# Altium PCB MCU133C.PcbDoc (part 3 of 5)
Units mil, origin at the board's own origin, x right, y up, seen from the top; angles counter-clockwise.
Board outline 2300 x 5500 mil, 4 copper layers (Top Signal, GND, PWR, Bottom Signal), stack 61.6 mil thick; 278 components, 226 nets, 1057 pads, 868 vias.
Unrouted connection lines stored in the file: 237.
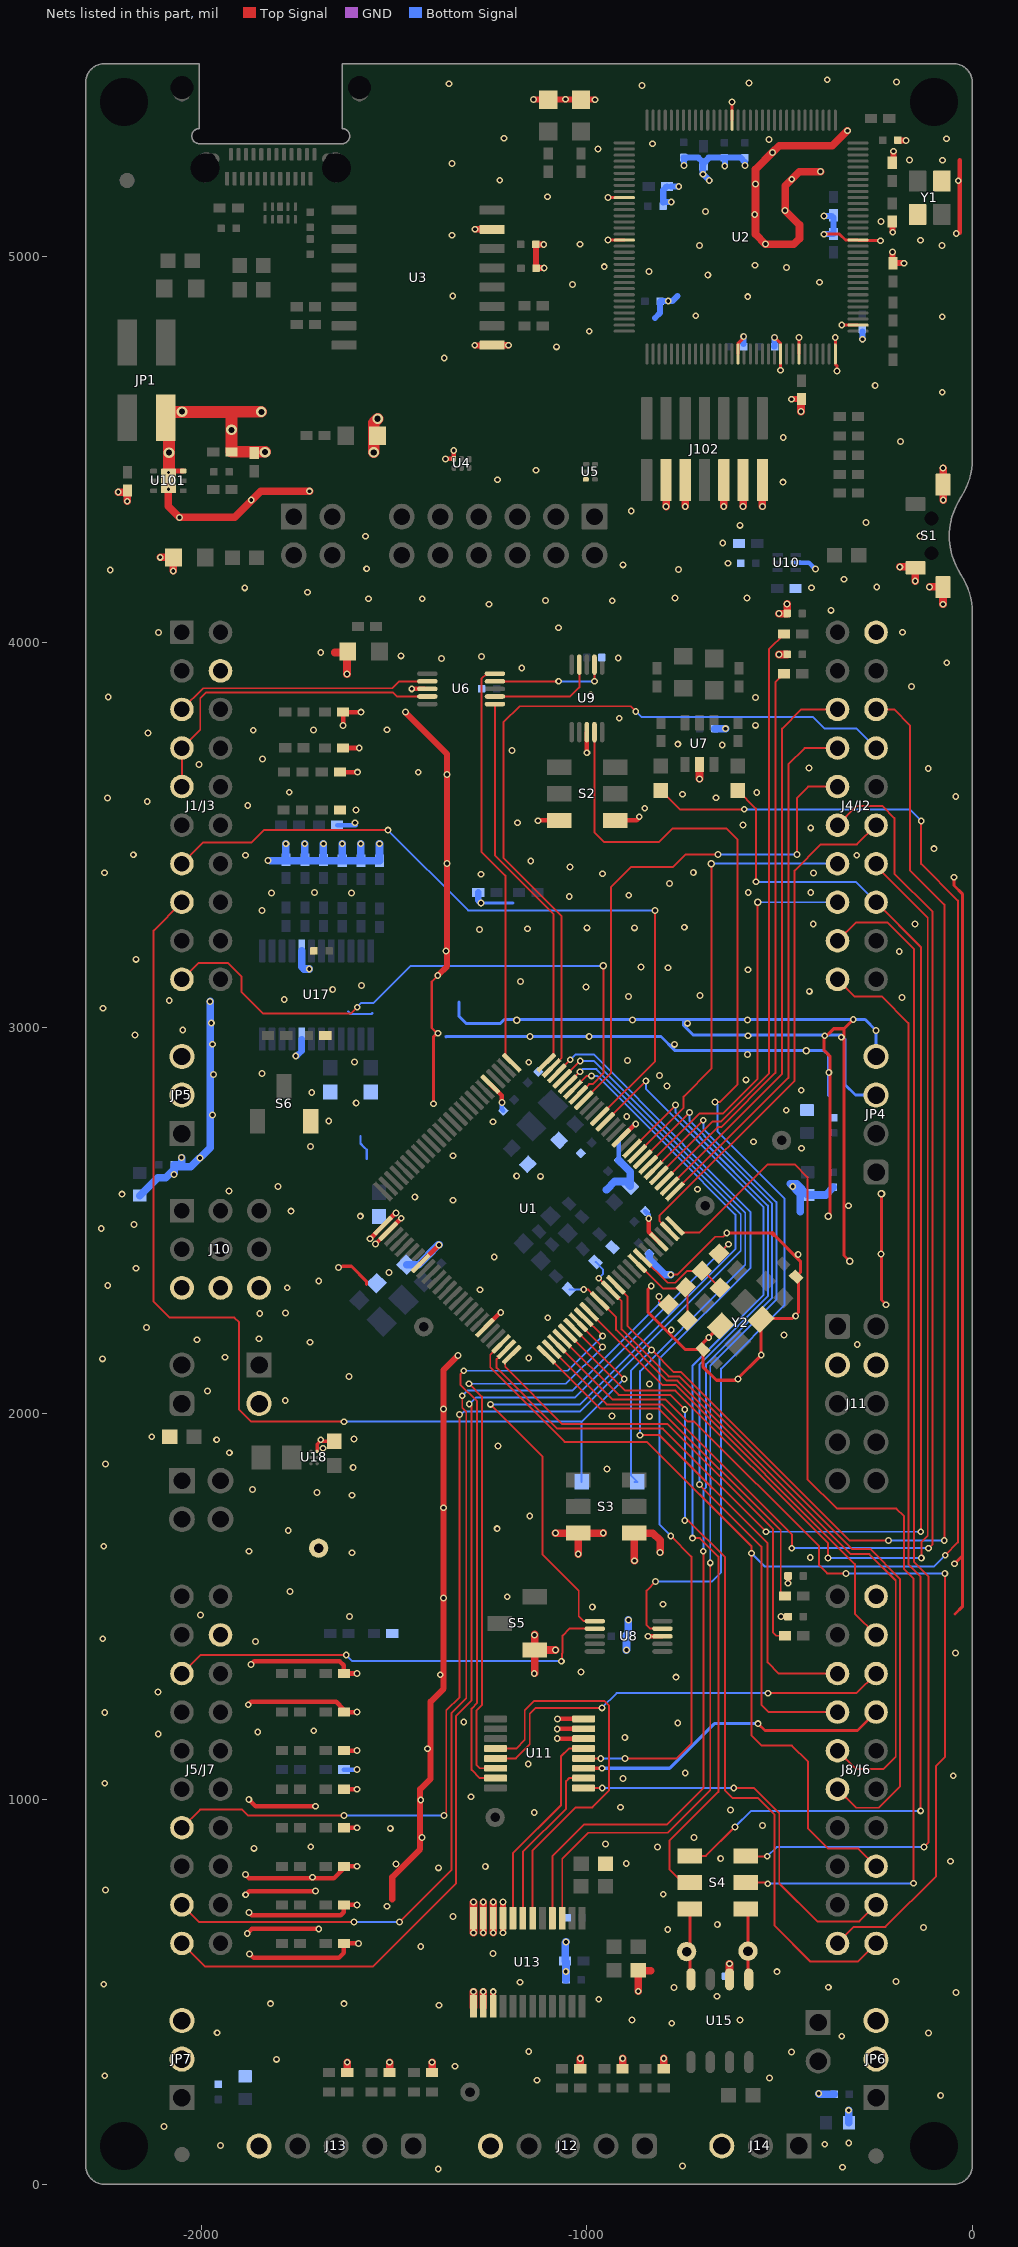
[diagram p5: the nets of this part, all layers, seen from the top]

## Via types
v1: diameter 17.72, hole 9.84, Top Signal to Bottom Signal, tented both sides, 822 vias
v2: diameter 19.68, hole 11.81, Top Signal to Bottom Signal, tented both sides, 22 vias
v3: diameter 27.56, hole 15.75, Top Signal to Bottom Signal, tented both sides, 17 vias
v4: diameter 15.75, hole 7.87, Top Signal to Bottom Signal, tented both sides, 5 vias
v5: diameter 19.68, hole 7.87, Top Signal to Bottom Signal, tented both sides, 2 vias

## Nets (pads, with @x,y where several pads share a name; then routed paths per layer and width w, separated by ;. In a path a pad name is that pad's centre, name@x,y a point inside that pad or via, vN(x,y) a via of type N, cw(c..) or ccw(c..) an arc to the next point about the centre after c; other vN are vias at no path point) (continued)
GND: C1.1 C2.1 C6.2 C7.2 C9.1 C10.1 C11.1 C12.1 C14.1 C15.2 C16.2 C17.2 C18.1 C19.1 C20.1 C21.1 C22.1 C24.2 C25.2 C26.2 C27.2 C28.2 C29.2 C30.2 C31.2 C32.2 C33.2 C34.2 C35.2 C36.2 C37.2 C38.2 C39.2 C40.2 C41.2 C42.2 C43.2 C44.1 C45.2 C46.1 C50.1 C51.1 C52.1 C53.1 C54.1 C55.1 C56.2 C57.2 C58.1 C59.2 C60.1 C61.2 C62.2 C63.2 C64.2 C65.1 C66.1 C67.2 C68.2 C69.2 C70.2 C71.2 C72.2 C73.2 C74.2 C75.2 C76.2 C77.2 C78.2 C81.1 C82.1 C83.1 C84.1 C100.2 C103.2 C107.2 C108.2 C109.2 C110.2 C111.1 C112.1 C113.1 C114.2 C115.1 C116.2 C117.1 C118.2 C119.1 C120.2 C121.2 C122.2 J1/J3.22 J4/J2.20 J5/J7.62 J8/J6.60 J10.7 J10.8 J10.9 J11.3 J11.4 J12.5 J13.5 J14.3 J15.2 J102.3 J102.5 J102.9 J102.11 J102.13 JP1.4 JP4.3 JP4.4 JP5.2 JP5.3 JP6.2 JP6.3 JP7.2 JP7.3 LED0.1 LED1.1 LED2.2 LED3.2 LED6.1 R52.1 R53.2 R67.1 R68.1 R83.2 R102.1 R107.2 R108.2 S1.1 S1.2 S1.3 S2.3 S2.6 S3.1 S3.4 S5.1 S6.3 TP6.1 U1.5 U1.26 U1.27 U1.33 U1.45 U1.72 U1.86 U2.10 U2.17 U2.48 U2.55 U2.58 U2.64 U2.66 U2.80 U2.114 U3.9 U3.15 U4.3 U5.3 U6.3 U7.2 U8.3 U9.3 U10.5 U11.6 U11.7 U11.8 U13.9 U13.10 U13.11 U13.12 U13.13 U13.14 U13.15 U15.2 U17.5 U17.20 U18.A2 U101.3 U101.7@-2085.04,4418.27 Y1.2 Y1.4 Y2.2 Y2.4 | length 22667.5
  Top Signal w5: v1(-782.31,2359.83) -765.19,2359.83 -666.81,2458.2 -646.86,2458.2 v1(-637.35,2467.71)
  Top Signal w5.91: v1@-1388.72,2985.69 -1402.4,2999.37 -1402.4,3119.45 v1(-1386.55,3135.3)
  Top Signal w7.87: -1634.09,2381.65 -1610.59,2381.65 -1571.69,2342.76 -1571.69,2334.7 ; v1(-1397.48,2803.03) -1397.48,2976.93 v1@-1388.72,2985.69 ; v1(-945.35,5042.68) U2.17@-902.99,5042.68 ; v1(-945.35,5152.91) U2.10@-902.99,5152.91 ; v1(-833.04,2330.31) -842.04,2321.31 -842.04,2262.94 -745.23,2166.13 C41.2@-699.1,2166.13 ; Y2.4@-653.72,2227.02 -699.1,2181.64 C41.2@-699.1,2166.13 ; v1(-637.35,2467.71) -519.2,2467.71 ; U2.114@-623.46,5353.7 v1(-623.46,5400.55) ; U2.48@-607.72,4747.4 -607.72,4775.36 -593.39,4789.69 v1(-593.39,4792.87) ; -514.77,2463.29 -446.45,2394.96 -446.45,2365.21 C42.2@-457.34,2354.32 -451.04,2348.03 -451.04,2262.05 -466.91,2246.18 -545.48,2246.18 Y2.2@-547.93,2243.72 v1(-547.93,2151.17) -613.05,2086.05 -664.04,2086.05 -699.1,2121.12 C41.2@-699.1,2166.13 ; v1(-513.15,4790.35) -513.07,4790.35 -497.48,4774.76 v1(-497.48,4705.04) ; U2.58@-450.24,4747.4 v1(-450.24,4789.76) ; v1(-385.04,5058.03) -344.58,5058.03 -329.23,5042.68 U2.80@-296.69,5042.68 -295.51,5041.5 -238.96,5041.5 v1(-238.62,5041.16) ; v2@-370.04,2515.29 -370.04,2926.55 -385.04,2941.55 -385.04,2972.55 -360.04,2997.55 -333.04,2997.55 ; v1(-355.75,4789.76) U2.64@-355.75,4747.4 -355.75,4720.87 -351.06,4716.18 v1(-351.06,4702.87) ; v1(-339.05,4822.2) U2.66@-296.69,4822.2 ; v2(-318.04,2394.69) -333.04,2409.69 -333.04,2997.55 ; v1(-309.04,3021.55) -333.04,2997.55 ; v2(-236.04,2569.23) -236.04,2293.94 v1(-224.04,2281.94) ; v1(-48.04,3390.55) -48.04,3368.81 -25.43,3346.21 -25.43,1631.56 ; v1(-46.59,1610.39) -25.43,1631.56 ; -45.41,1479.69 -25.43,1499.67 -25.43,1631.56 ; -25.43,1682.95 -25.43,1631.56
  Top Signal w9.06: U18.A2@-1699.64,1901.5 -1699.64,1920.15 -1692.03,1927.75 C110.2@-1655.02,1927.75
  Top Signal w11.81: U101.7@-2085.04,4418.27 -2085.04,4428.78 -2083.5,4430.32 -2069.96,4443.86 U101.3@-2046.65,4443.86 ; v1(-1885.18,804) -1876.12,794.94 -1655.85,794.94 -1630.04,820.75 C75.2@-1630.04,825.55 v1(-1596.04,825.55) ; v1(-1884.78,751.83) -1875.24,761.38 v1(-1703.98,761.38) ; v1(-1880.75,651.63) -1869.23,663.15 v1(-1695.41,663.15) ; v1(-1877.89,1244.65) -1870.51,1252.03 -1649.94,1252.03 -1630.04,1232.13 C37.2@-1630.04,1225.55 v1(-1596.04,1225.55) ; v1(-1876.54,998.98) -1859.12,981.56 v1(-1703.58,981.56) ; v1(-1876.32,706.16) -1868.74,698.58 -1638.03,698.58 -1630.04,706.58 C38.2@-1630.04,725.55 v1(-1596.04,725.55) ; v1(-1874.65,598.48) -1864.31,588.15 -1642.85,588.15 -1630.04,600.96 C25.2@-1630.04,625.55 -1592.14,625.55 v1(-1592.04,625.45) ; v1(-1871,1349.27) -1862.44,1357.83 -1641.28,1357.83 -1630.04,1346.59 C107.2@-1630.04,1325.55 v1(-1596.04,1325.55) ; C31.2@-1640.2,3662.93 v1(-1595.04,3662.93) ; C39.2@-1632.13,3725.55 -1590.47,3725.55 v1(-1590.15,3725.87) ; v1@-1632.05,3783.9 C28.2@-1632.05,3818.85 -1586.34,3818.85 v1(-1586.04,3818.55) ; C40.2@-1630.04,925.55 v1(-1596.04,925.55) ; C27.2@-1630.04,1025.55 v1(-1596.04,1025.55) ; C35.2@-1630.04,1125.55 v1(-1596.04,1125.55) ; v1(-1562.1,2453.13) U1.26@-1528.67,2486.56 v1(-1495.24,2519.99) ; v1(-1548.18,2439.21) U1.27@-1514.75,2472.64 v1(-1481.32,2506.07) ; v1(-1454.05,3879.01) U6.3@-1420.15,3879.01 ; U1.33@-1431.23,2389.12 -1383.21,2437.14 v1(-1383.04,2437.14) ; v1(-1366.3,4475.12) -1345.08,4475.12 U4.3@-1344.65,4475.55 ; U4.3@-1345.08,4475.98 v1(-1345.08,4497.2) ; U1.45@-1264.2,2222.09 v1@-1224.61,2261.68 ; U1.5@-1250.28,2854.03 -1220.71,2824.46 -1220.71,2806.5 v1(-1220.22,2806.01) ; v1@-1128.76,3537.97 S2.3@-1071.81,3537.97 ; v1(-1076.91,1181.95) -1076.61,1182.24 U11.7@-1008.4,1182.24 ; v1(-1076.71,1157.15) -1076.22,1156.65 U11.6@-1008.4,1156.65 ; v1(-1075.83,1207.62) -1075.61,1207.83 U11.8@-1008.4,1207.83 ; v1(-1000.04,3713.17) -999.93,3713.28 U9.3@-999.93,3766.68 ; S2.6@-926.14,3537.97 -870.7,3537.97 v1@-862.62,3546.05 ; U1.86@-910.64,2714.84 -874.93,2750.55 v1(-873.04,2750.55) v1@-873.04,2751.26 ; v1(-841.08,1422.07) U8.3@-803.95,1422.07 ; v1(-839.41,2505.67) -839.41,2471 U1.72@-813.21,2444.8 ; -519.2,2467.71 -514.77,2463.29 ; v1(-496.5,1473.19) C81.1@-478.31,1473.19 ; C82.1@-478.29,1578.5 -478.29,1559.61 v1(-478.19,1559.51) ; -33.04,5061.47 -33.04,5249.55
  Top Signal w15.75: -1504.67,740.22 -1504.67,797.7 -1432.42,869.94 -1432.42,1025.65 -1405.35,1052.72 -1405.35,1252.32 -1371.51,1286.16 -1371.51,2112.93 v1(-1334.39,2150.06) ; v1(-1470.51,3819.06) -1470.51,3817.87 -1362.44,3709.8 -1362.44,3160.1 v1@-1386.9,3135.64 ; v1(-1290.59,4769.84) U3.9@-1270.75,4769.84 ; v1(-1289.8,5070.79) U3.15@-1244.45,5070.79 ; U13.15@-1242.87,460.69 v1(-1242.87,500.57) ; U3.9@-1222.72,4770 v1(-1202.87,4770) ; v1(-1217.28,653.11) U13.9@-1217.28,692.99 ; U13.9@-1217.28,692.97 v1(-1217.28,732.85) ; v1(-1138.15,5406.93) LED3.2@-1118.31,5406.93 ; C1.1@-1132.09,5026 -1132.09,4970.67 C2.1@-1131.34,4969.92 ; C1.1@-1132.09,5031 v1(-1111.72,5031) ; C2.1@-1130.55,4970.63 v1(-1110.71,4970.63) ; LED3.2@-1090.24,5407.8 LED2.2@-1035.47,5407.8 ; LED2.2@-998.43,5406.73 v1(-978.58,5406.73) ; v1(-469.49,4630.08) R68.1@-449.65,4630.08 ; R67.1@-207.36,4991.89 v1(-207.36,5011.73) ; v1(-206.97,5063.15) C62.2@-206.97,5082.99 ; C63.2@-205,5253.11 v1(-205,5272.95) ; R67.1@-197.36,4982.8 v1(-177.52,4982.8) ; C50.1@-192.48,5300.79 v1(-172.64,5300.79)
  Top Signal w19.68: v1(-2215.39,4389.13) -2191.93,4389.13 v1(-2191.93,4365.67) ; v1(-2106.45,4219.99) LED6.1@-2072.55,4219.99 ; U101.7@-2085.04,4418.27 -2085.04,4352.13 v1(-2056.42,4323.5) -1913.58,4323.5 -1845.43,4391.65 -1845.39,4391.61 v1(-1719.25,4391.61) ; v1(-2072.55,4184.77) LED6.1@-2072.55,4218.67 ; -1653.82,3973.31 LED1.1@-1622.6,3973.31 ; v1@-1621.97,3917.3 -1621.97,3972.68 LED1.1@-1622.6,3973.31 ; C73.2@-1621.42,290.55 v1(-1621.42,317.28) ; LED1.1@-1620.35,3975.55 LED1.1@-1622.6,3973.31 ; C72.2@-1511.42,290.55 v1(-1511.42,317.28) ; C71.2@-1401.42,290.55 v1(-1401.42,317.28) ; U13.13@-1294.06,460.69 v1(-1294.05,500.57) ; v1(-1294.05,653.11) U13.12@-1294.05,692.99 ; U13.12@-1294.06,692.97 v1(-1294.05,732.85) ; U13.14@-1268.46,460.69 v1(-1268.46,500.57) ; U13.11@-1268.46,692.97 v1(-1268.46,732.85) ; U13.11@-1268.46,692.99 v1(-1268.46,653.11) ; v1(-1242.87,653.11) U13.10@-1242.87,692.99 ; U13.10@-1242.87,692.97 v1(-1242.87,732.85) ; v1@-1135.43,1326.28 S5.1@-1135.43,1386.7 ; v1@-1135.43,1426.95 S5.1@-1135.43,1386.7 ; v1(-1081.28,1386.55) -1135.28,1386.55 S5.1@-1135.43,1386.7 ; v1(-1081.28,1689.61) S3.4@-1022.6,1689.61 ; v1(-1022.44,1635.37) -1022.6,1635.53 S3.4@-1022.6,1689.61 ; C70.2@-1017.17,300.55 v1(-1017.17,327.28) ; v1(-957.69,1690.02) -958.11,1689.61 S3.4@-1022.6,1689.61 ; C69.2@-907.17,300.55 v1(-907.17,327.28) ; v1(-876.54,1617.8) -876.93,1618.18 S3.1@-876.93,1689.61 -828.77,1689.61 -810.03,1670.87 v1(-810.03,1639.55) ; v1(-866.79,501.53) R53.2@-866.79,555.55 -865.61,556.73 -863.25,554.37 -834.29,554.37 ; S3.1@-866.73,1689.06 -829.21,1689.06 ; C68.2@-800.43,300.55 v1(-800.43,327.28) ; J102.3@-794.84,4420.43 -794.61,4420.2 v1(-794.61,4351.77) ; v1(-744.84,4352.01) J102.5@-744.84,4420.43 ; v1(-708,3645.42) U7.2@-708,3682.94 ; v1(-644.84,4352.01) J102.9@-644.84,4420.43 ; U15.2@-630.16,532.52 v1(-630.16,573.13) ; v1(-594.84,4352.01) J102.11@-594.84,4420.43 ; v1(-544.84,4352.01) J102.13@-544.84,4420.43 ; v1(-502.05,3967.95) C83.1@-480.71,3967.95 ; v1(-502.05,4074.02) C84.1@-480.71,4074.02 ; C84.1@-480.71,4074.49 v1(-480.71,4099.09) ; v1(-444.64,4597.88) R68.1@-444.64,4631.78 ; v1(-394.13,5220.24) -448.62,5220.24 v1(-468.54,5200.32) -485.87,5182.99 v1(-485.87,5119.35) -448.62,5082.11 -448.62,5046.47 -463.63,5031.46 -536.06,5031.46 v1(-537.05,5032.44) -562.64,5058.03 v1(-562.64,5187.95) -562.64,5225.99 v1(-518.78,5269.84) -501.46,5287.17 -363.23,5287.17 v1(-324.25,5326.14) ; v1(-188.38,4195.27) S1.3@-154.48,4195.27 ; v1(-148.26,4158.31) S1.3@-148.26,4192.21 ; v1(-111.29,4143.34) S1.1@-77.4,4143.34 ; v1(-76.53,4098.36) S1.1@-76.53,4132.25 ; S1.2@-76.23,4417.59 v1(-76.23,4451.49) ; v1(-75.83,4368.66) S1.2@-75.83,4402.56
  Top Signal w30: U101.7@-2083.5,4430.32 v3(-2083.5,4491.42) -2083.5,4573.61 JP1.4@-2092.01,4582.11 -2077.31,4596.81 -1930.04,4596.81 ; v3(-1844.05,4597.09) -1929.76,4597.09 -1930.04,4596.81 ; v3@-1833.54,4493.55 R102.1@-1921.42,4493.55 -1921.42,4588.19 -1930.04,4596.81 ; v3(-1552.7,4492.24) -1552.7,4568.69 -1542.32,4579.07 v3(-1542.7,4579.45)
  Bottom Signal w5.91: -1619.04,3042.09 -1612.74,3035.79 -1558.6,3035.79 -1555.94,3038.44 ; -1587.19,2719.15 -1587.19,2699.7 -1577.76,2690.26 ; -1577.76,2690.21 -1571.04,2683.5 -1571.04,2659.65
  Bottom Signal w7.87: -1365.67,2976.55 -1364.67,2977.55 v1(-994.04,2977.55) -807.89,2977.55 -770.89,2940.55 v2(-431.04,2940.55) -384.04,2940.55 -373.04,2929.55 -373.04,2824.55 ; -1331.11,3066.55 -1331.11,3029.05 -1313.61,3011.55 -1224.04,3011.55 -1214.04,3021.55 -749.25,3021.55 ; v1(-1274.47,3323.55) -1191.59,3323.55 ; JP4.3@-250.04,2825.55 -303.54,2825.55 -330.35,2852.37 -330.35,2971.14 -340.08,2980.87 -723.57,2980.87 -749.25,3006.55 -749.25,3021.55 ; JP4.4@-250.04,2925.55 v1(-250.04,2993.23) -278.36,3021.55 v1(-309.04,3021.55) -749.25,3021.55
  Bottom Signal w11.81: C36.2@-1647.8,3525.55 v1@-1598.99,3525.55 ; C29.2@-1630.04,1076.55 v1(-1596.04,1076.55) ; v1(-1220.22,2806.01) -1220.22,2788.72 C10.1@-1216.63,2785.13 ; C11.1@-917.32,2656.45 -917.32,2708.32 -875.09,2750.55 v1(-873.04,2750.55) ; C12.1@-848.7,2524.72 -839.41,2515.43 v1(-839.41,2505.67) ; U10.5@-458.12,4206.55 -424.65,4206.55 -407.65,4189.55 v1(-407.04,4189.55)
  Bottom Signal w15.75: v1(-1754.97,2926.98) -1752.25,2926.98 -1739.39,2939.84 U17.20@-1739.39,2970.98 ; -823.27,4840.71 -809.92,4854.06 C55.1@-809.92,4883.66 ; C55.1@-808.94,4884.65 v1(-789.09,4884.65) -778.15,4884.65 -765.39,4897.4 ; -801.97,5140.63 -801.97,5172.44 C57.2@-792.44,5181.97 ; -800.98,5141.61 v1(-781.14,5141.61) ; C57.2@-781.42,5181.3 v1(-761.57,5181.3) ; C52.1@-749.25,5256.77 -715.14,5256.77 -714.95,5256.58 -710.59,5256.58 -701.37,5247.35 -701.37,5242.8 C61.2@-697.43,5238.86 ; v1(-748.27,5235.94) C52.1@-748.27,5255.79 ; C61.2@-695.89,5241.88 -695.89,5244.34 C61.2@-693.49,5246.74 ; v1(-682.4,5197.43) -699.4,5214.42 -699.4,5246.25 -693.98,5246.25 C61.2@-693.49,5246.74 ; -682.4,5256.58 -682.4,5255.96 -691.63,5246.74 C61.2@-693.49,5246.74 ; v1(-642.2,5234.96) C60.1@-642.2,5254.8 ; -602.05,5256.77 -679.72,5256.77 -679.91,5256.58 -684.27,5256.58 -693.49,5247.35 C61.2@-693.49,5246.74 ; -601.06,5255.79 -590.04,5244.76 v1(-590.04,5235.94) ; C54.1@-593.39,4773.03 v1(-593.39,4792.87) ; C53.1@-514.06,4766.81 -513.15,4767.72 v1(-513.15,4790.35) ; v1(-385.04,5058.03) C56.2@-365.2,5058.03 ; v1(-385.04,5105.32) -365.2,5105.32 -360.83,5100.94 C56.2@-360.83,5058.31 ; v1(-285.51,4785.47) C66.1@-285.51,4805.32
  Bottom Signal w17.72: C17.2@-1281.66,3350.95 -1281.66,3330.74 v1(-1274.47,3323.55)
  Bottom Signal w19.68: C115.1@-2159.57,2564.66 -2112.76,2611.48 -2092.26,2611.48 -2070.35,2633.39 C116.2@-2070.35,2644.55 ; v1@-2070.35,2623.98 C116.2@-2070.35,2644.55 ; v1(-2051.04,2663.55) -2051.04,2644.55 C116.2@-2070.35,2644.55 ; v1(-1977.04,3068.55) -1977.04,2689.4 -2027.2,2639.23 -2065.04,2639.23 C116.2@-2070.35,2644.55 ; v1@-1821.34,3433.25 C76.2@-1634.34,3433.25 ; v1@-1780.57,3476.58 -1780.57,3436.3 C26.2@-1779.95,3435.67 ; U17.5@-1739.39,3199.32 -1739.39,3158.35 -1733.56,3152.52 v1(-1719.92,3152.52) ; C34.2@-1731.34,3435.76 v1@-1731.34,3476.6 ; C32.2@-1683.26,3435.59 v1(-1683.26,3477.1) ; v1(-1634.34,3477.1) C76.2@-1634.34,3433.25 ; v1(-1586.18,3477.1) C78.2@-1586.18,3433.25 ; v1(-1537.7,3477.1) C77.2@-1537.7,3433.25 C78.2@-1586.18,3433.25 ; C15.2@-1467.48,2385.5 -1436.41,2385.5 -1384.77,2437.14 v1(-1383.04,2437.14) ; C65.1@-1053.98,531.06 -1053.98,577.44 C67.2@-1056.26,579.72 -1056.26,627.27 v1(-1053.98,629.55) ; -949.04,2580.38 -927.87,2601.55 -898.98,2601.55 C9.1@-886.98,2589.55 -886.98,2626.11 C11.1@-917.32,2656.45 ; v1(-897.33,1386.55) -897.09,1386.78 C45.2@-897.09,1422.07 -892.16,1427.01 v1(-892.16,1464.3) ; C21.1@-838.12,2414.03 -838.12,2399.57 -798.38,2359.83 v1(-782.31,2359.83) ; C44.1@-668.35,3776.02 -668.08,3775.75 v1(-640.24,3775.75) ; -446.3,2523.09 -446.3,2568.42 -473.04,2595.16 -456.33,2595.16 C111.1@-427.54,2566.37 -380.85,2566.37 C112.1@-361.04,2586.18 ; v1(-398.46,236.18) -396.83,234.55 C118.2@-358.7,234.55 ; v1(-321.1,192.87) -320.51,192.28 C117.1@-320.51,160.55 ; C76.2@-1634.34,3433.25 C78.2@-1586.18,3433.25
  other v1: -1385.16,40.79 -337.05,45.04 -751.81,48.19 -1950.04,101.81 -382.91,104.88 -320.91,108.13 -2096.22,150.98 -82.54,231.55 -1129.21,270.67 -526.4,277.03 -2250.04,282.55 -1342.13,307.09 -1804.61,325.04 -469.43,344.35 -1150.47,345.67 -339.02,384.72 -1958.7,394.02 -113.72,393.37 -779.65,418.43 -882.76,427.32 -603.19,427.32 -1383.27,465.12 -1820.75,469.45 -1630.04,469.45 -969.02,480.87 -662.68,488.82 -42.36,498.62 -773.7,511.61 -373.78,511.89 -2252.76,519.57 -1173.43,525.16 -198.19,526.77 -506.89,552.4 -1054.49,553.15 -1243.04,599.55 -1430.85,617.58 -790.04,661.5 -127.2,666.59 -661.6,674.55 -1347.45,695.37 -1518.15,721.91 -801.78,753.22 -2247.87,764.45 -1711.16,797.2 -1384.57,821.61 -1263.23,824.96 -1494.72,831.75 -897.66,832.55 -56.83,838.84 -653.04,846.05 -1863.13,872.2 -817.04,875.37 -1715.89,876.44 -951.31,883.62 -1427.6,900.26 -722.04,900.58 -1509.59,924.07 -544.29,931.55 -1136.26,965.32 -627.48,971.55 -912.56,978.55 -1430.75,997.5 -1300.14,1006.06 -2250.31,1041.14 -906.16,1053.55 -50.04,1060.3 -744.8,1067.6 -1152.01,1091.2 -1413.54,1130.57 -901.52,1159.8 -2111.34,1168.82 -1853.39,1173.58 -1708.11,1177.32 -764.31,1196.91 -1319.33,1199.57 -2250.31,1224.76 -2112.44,1277.95 -769.04,1316.1 -1380.12,1322.2 -1136.26,1325.55 -1015,1329.19 -43.84,1378.9 -1859.04,1408.3 -2255.2,1415.79 -1135.43,1425.55 -1615.7,1473.55 -2002.04,1477.55 -985.77,1498.05 -802.23,1505.3 -1371.51,1521.22 -1206.32,1524.6 -1770.04,1538.05 -420.81,1626.63 -1608.78,1638.55 -1876.04,1642.55 -2252.76,1655.75 -1774.21,1696.59 -1232.61,1701.2 -1148.04,1734.02 -1371.51,1755.47 -1609.36,1787.82 -1699.55,1794.65 -1867.04,1802.72 -947.42,1856.05 -1606.04,1859.55 -2247.87,1868.78 -1927.11,1897.89 -1684.04,1909.55 -1230.44,1915.38 -1959.98,1931.75 -1690.04,1931.55 -1604.04,1933.55 -2128.39,1939.72 -837.63,1992.45 -935.06,1993.14 -1371.51,2011.77 -1782.04,2033.55 -1983.88,2057.97 -837.3,2076.63 -608,2089.55 -1617.04,2095.55 -2256.04,2141.55 -1150.47,2143.55 -1938.04,2145.55 -298.94,2178.55 -1718.04,2184.55 -2011.14,2191.19 -1850.04,2193.55 -684.04,2196.7 -488.7,2203.45 -781.04,2216.2 -2142.04,2222.55 -1101.48,2248.02 -458.54,2252.55 -1848.04,2259.05 -1781.54,2260.41 -1223.44,2261.68 -1277.04,2320.81 -1777.04,2325.81 -2242.54,2331.66 -1695.12,2343.76 -1513.04,2365.57 -2169.04,2376.55 -1644.04,2378.8 -1239.96,2405.4 -452.04,2411.98 -236.85,2413.54 -2259.13,2479.89 -2174.04,2489.84 -1587.41,2511.55 -1767.04,2524.55 -321.52,2538.55 -1347.04,2552.91 -1446.04,2561.55 -2205.54,2568.64 -1927.99,2576.93 -713.25,2581.43 -1800.63,2588.44 -466.18,2588.18 -1120.04,2614.83 -1182.04,2616.02 -2070.35,2619.94 -2003.48,2662.46 -1347.04,2668.08 -443.04,2687.55 -1716.38,2692.57 -567.54,2704.67 -1243.04,2756.55 -1669.53,2758.55 -896.55,2770.38 -1970.61,2773.99 -483.04,2786.22 -1598.27,2805.25 -1713.31,2832.46 -444.04,2838.05 -791.88,2848.74 -587.04,2865.05 -811.31,2876.22 -1968.54,2878.8 -1842.66,2881.85 -372.48,2884.11 -1150.65,2910.55 -1602.51,2911.55 -894.4,2915.48 -583.04,2930.55 -1971.1,2957.44 -773.04,2957.13 -340.08,2975.55 -1147.78,2977.82 -582.44,2979.55 -383.12,2979.55 -2172.04,2981.55 -1386.26,2985.69 -2048.04,2994.55 -739.13,3011.55 -1973.76,3012.26 -881.88,3020.22 -583.42,3020.55 -2255.04,3050.55 -2083.04,3070.55 -1784.78,3073.68 -182.58,3078.55 -892.35,3081.48 -706.73,3083.55 -423.04,3094.55 -1659.19,3099.37 -1002.51,3105.55 -1584.47,3109.61 -1171.72,3119.73 -582.44,3150.55 -789.54,3155.74 -859.53,3157.71 -2169.04,3177.55 -189.82,3197.55 -1364.9,3199.17 -1278.12,3254.55 -1153.72,3257.02 -999.59,3259.24 -876.15,3259.24 -747.21,3260.55 -413.04,3269.55 -149.04,3269.55 -1842.04,3304.55 -1045.66,3340.55 -891.29,3343.55 -1818.04,3349.55 -1610.16,3349.55 -1706.54,3350.55 -581.42,3350.95 -419.42,3350.95 -786.04,3374.55 -1274.47,3398.14 -959.5,3399.44 -2251.02,3402.01 -412.33,3401.55 -723.84,3403.03 -1043.43,3417.1 -1362.44,3426.24 -1145.47,3432.55 -1827.04,3433.55 -1885.04,3447.55 -300,3447.55 -2176.04,3448.55 -100.04,3464.55 -1780.57,3477.1 -1731.34,3477.1 -419.42,3518.55 -595.04,3525.55 -1601.32,3531.95 -1180.04,3531.95 -1126.98,3536.99 -863.96,3547.42 -1598.99,3564.92 -850.04,3569.55 -1879.27,3576.7 -2140.04,3586.55 -2243.04,3595.55 -665.04,3596.55 -43.54,3599.55 -752.04,3605.55 -1771.89,3610.89 -559.53,3610.55 -1362.44,3656.65 -1437.04,3662.55 -114.85,3672.55 -423.7,3673.55 -2005.45,3682.94 -1841.38,3696.91 -1194.12,3719.42 -649.04,3733.24 -764.04,3735.55 -2138.04,3764.55 -1864.99,3771.55 -1709.04,3772.55 -1518.04,3773.05 -1632.04,3783.9 -562.64,3784.32 -916.12,3802.55 -562.64,3856.55 -2241.04,3857.55 -990.04,3863.01 -158.04,3885.24 -1622.13,3917.3 -1168.69,3932.8 -66.85,3946.81 -1377.04,3957.55 -918.76,3959.3 -1273.14,3962.55 -1482.04,3964.55 -1690.04,3973.55 -2110.57,4025.16 -181.29,4025.8 -1073.65,4037.3 -367.04,4082.55 -1254.04,4098.55 -934.04,4107.55 -1107.57,4108.06 -1566.04,4112.55 -1427.04,4112.55 -771.45,4114.55 -585.04,4114.55 -1724.54,4129.55 -1887.15,4140.91 -417.57,4140.98 -248.29,4143.34 -333.04,4163.17 -2236.04,4187.55 -762.04,4188.83 -1571.04,4190.55 -906.1,4200.55 -633.98,4204.55 -647.78,4257.55 -1574.04,4274.55 -135.99,4275.55 -602.91,4302.97 -275.91,4310.51 -884.99,4340.3 -1870.31,4368.39 -491.73,4414.96 -1231.81,4421.3 -1132.17,4445.79 -186.97,4520.16 -490.83,4530.79 -78.5,4647.91 -252.36,4665.75 -1369.8,4736.77 -1078.78,4765.87 -993.74,4806.46 -78.5,4843.86 -717.76,4846.69 -582.64,4895.98 -1347.91,4897.95 -1037.05,4927.28 -396.5,4933.23 -686.26,4952.13 -838.62,4961.57 -481.93,4971.81 -954.76,4973.78 -564.33,4977.6 -707.52,5028.9 -78.7,5028.31 -1017.8,5031.77 -134.54,5042.08 -1349.84,5055.12 -42.28,5059.55 -237.04,5090.55 -564.61,5109.17 -692.17,5117.2 -1102.04,5155.24 -37.04,5196.55 -1225.83,5198.07 -698.93,5213.27 -1349.84,5241.06 -78.04,5249.86 -163.04,5250.55 -971.1,5278.9 -829.45,5292.36 -527.87,5303.9 -67.68,5305.35 -1214.53,5306.66 -1055.31,5407.8 -856.81,5443.54 -1357.52,5448.07 -579.84,5449.69 -197.13,5452.87 -376.42,5458.44
  other v2: -373.78,2511.55 -1181.72,3019.55
  other v3: -1834.68,4492.8 -1921.38,4550.43 -2049.92,4597.72
  other v5: -2085.04,4396.61 -2085.04,4439.92
GPIO0: R8.1 U1.79 | length 1550.4
  Top Signal w5: U1.79@-813.21,2617.4 -673.06,2757.55 -651.91,2757.55 -528,2881.47 -528,3981.73 R8.1@-488.7,4021.02
GPIO1: R9.1 U1.78 | length 1448.5
  Top Signal w5: U1.78@-799.29,2603.48 -660.44,2742.33 -651.71,2742.33 -511.04,2883 -511.04,3895.93 R9.1@-488.7,3918.27
GPIO2: J4/J2.38 U1.77 | length 1471.4
  Top Signal w5: U1.77@-785.37,2589.56 -493.55,2881.38 -493.55,3776.04 -444.04,3825.55 J4/J2.38@-350.04,3825.55
GPIO3: J4/J2.37 U1.76 | length 1374.5
  Top Signal w5: U1.76@-771.45,2575.64 -477.22,2869.87 -477.22,3683.76 -435.43,3725.55 J4/J2.37@-350.04,3725.55
GPIO4: S4.2 U1.75 | length 2910
  Top Signal w5: U1.75@-771.45,2486.56 -753.63,2468.74 -708.35,2468.74 -531.36,2645.73 -460.98,2645.73 -427.85,2612.59 -427.85,1829.93 -350.93,1753.01 -197.5,1753.01 -177.23,1732.74 -177.23,1596.15 -152.7,1571.61 v1(-152.7,781.55) v1@-152.7,781.26 ; S4.2@-587.87,783.58 -534.07,783.58 v1(-531.04,780.55)
  Bottom Signal w5: v1(-531.04,780.55) -530.04,781.55 v1(-152.7,781.55)
GPIO4_BP: J4/J2.32 S4.3 | length 3136.3
  Top Signal w5: S4.3@-587.87,852.48 -586.94,851.55 v1(-532.04,851.55) ; J4/J2.32@-350.04,3225.55 -302.04,3273.55 -221.04,3273.55 -151.91,3204.42 -151.91,3046.42 -151.91,1615.02 ; -151.91,1683.23 -151.91,1615.02 ; v1(-126.04,875.55) -114.31,887.28 -114.31,1577.42 -151.91,1615.02
  Bottom Signal w5: v1(-532.04,851.55) -508.04,875.55 v1(-126.04,875.55)
GPIO4_CANTX: S4.1 TP7.1 U15.1 | length 184.4
  Top Signal w7.87: U15.1@-582.44,532.52 -582.44,605.55 -582.44,638.62 S4.1@-582.44,709.25
  Top Signal w19.68: S4.1@-587.87,714.69 S4.1@-582.44,709.25
GPIO5: S4.5 U1.89 | length 2554.4
  Top Signal w5: U1.89@-952.4,2756.6 v1(-847.04,2861.96) ; S4.5@-733.54,783.58 -751.22,783.58 -786.04,818.4 -786.04,891.55 -658.8,1018.79 -658.8,1628.73 -706.62,1676.55 v1(-726.04,1676.55)
  Bottom Signal w5: v1(-847.04,2861.96) -847.04,2841.5 -716.21,2710.67 -716.21,2709.18 -541.47,2534.45 -541.47,2308.39 -726.04,2123.82 v1(-726.04,1676.55)
GPIO5_BP: J4/J2.31 S4.6 | length 2934.3
  Top Signal w5: S4.6@-733.54,852.48 -691.11,852.48 v1(-616.04,927.55) ; J4/J2.31@-350.04,3125.55 -306.04,3081.55 -235.62,3081.55 -166.32,3012.25 -166.32,1608.57 -134.49,1576.73 -134.49,969.52 v1(-134.42,969.45)
  Bottom Signal w5: v1(-616.04,927.55) -574.04,969.55 -134.52,969.55 v1(-134.42,969.45)
GPIO5_CANRX: S4.4 TP8.1 U15.4 | length 182.6
  Top Signal w7.87: U15.4@-732.44,532.52 -732.44,604.41 S4.4@-732.44,713.58
  Top Signal w11.81: S4.4@-733.54,714.69 S4.4@-732.44,713.58
GPIO6: J8/J6.78 U1.97 | length 2294.8
  Top Signal w5: U1.97@-1063.76,2867.95 -1018.16,2913.55 v1(-1017.04,2913.55) ; v1(-862.04,1943.55) -811.62,1943.55 -531.04,1662.97 -531.04,1354.55 -502.04,1325.55 J8/J6.78@-350.04,1325.55
  Bottom Signal w5: v1(-1017.04,2913.55) -980.78,2913.55 -759.83,2692.6 -759.83,2691.12 -589.27,2520.55 -589.27,2385.56 -806.97,2164.79 -862.04,2109.72 v1(-862.04,1943.55)
GPIO7: J8/J6.77 U1.84 | length 2158.9
  Top Signal w5: U1.84@-882.8,2687 v1(-770.04,2799.76) ; v1(-708.04,1815.55) -547.3,1654.82 -547.3,1244.82 -528.04,1225.55 J8/J6.77@-350.04,1225.55
  Bottom Signal w5: v1(-770.04,2799.76) -770.04,2779.92 -705.3,2715.19 -705.3,2713.7 -530.57,2538.97 -530.57,2303.87 -708.04,2126.4 v1(-708.04,1815.55)
GPIO8: J4/J2.15 U1.74 | length 1351.2
  Top Signal w5: U1.74@-785.37,2472.64 -812.04,2499.31 -812.04,2512.23 -461.04,2863.23 -461.04,3407.55 -392.87,3475.72 -299.87,3475.72 J4/J2.15@-250.04,3525.55
GPIO9: J1/J3.7 U1.90 | length 1942.6
  Top Signal w5: J1/J3.7@-2050.04,3425.55 -1995.04,3480.55 -1869.45,3480.55 -1837.45,3512.55 v1(-1516.04,3512.55) ; U1.90@-966.32,2770.51 -823.04,2913.8 v1(-823.04,3304.55)
  Bottom Signal w5: v1(-1516.04,3512.55) -1308.04,3304.55 v1(-823.04,3304.55)
GPIO10: J4/J2.36 U1.93 | length 1363.5
  Top Signal w5: U1.93@-1008.08,2812.27 -937.04,2883.31 -937.04,3365.55 -885.49,3417.1 -776.15,3417.1 -743.7,3449.55 v1(-660.04,3449.55) ; v1(-455.04,3449.55) -455.04,3596.55 -426.04,3625.55 J4/J2.36@-350.04,3625.55
  Bottom Signal w5: v1(-660.04,3449.55) v1(-455.04,3449.55)
GPIO11: J4/J2.35 U1.52 | length 3331.5
  Top Signal w5: U1.52@-1091.6,2166.41 -948.77,2023.58 -805.75,2023.58 -468.54,1686.38 v1(-468.54,1650.55) ; J4/J2.35@-350.04,3525.55 -300.79,3574.8 -233.29,3574.8 -202.54,3544.05 -202.54,3399.53 -103.65,3300.65 -103.65,1661.06 v1(-114.16,1650.55)
  Bottom Signal w5: v1(-468.54,1650.55) v1(-114.16,1650.55)
GPIO12: R49.1 U1.51 | length 971.6
  Top Signal w5: U1.51@-1105.52,2152.49 -965.7,2012.68 -813.15,2012.68 -497.18,1696.71 -497.18,1537.82 R49.1@-486.18,1526.81
GPIO13: R50.1 U1.50 | length 1210
  Top Signal w5: U1.50@-1194.6,2152.49 -1211.58,2135.51 -1211.58,2120.49 -1063.64,1972.55 -790.2,1972.55 -517.28,1699.62 -517.28,1431.75 -509.03,1423.5 R50.1@-486.18,1423.5
GPIO14: J5/J7.47 U1.96 | length 3383.7
  Top Signal w5: J5/J7.47@-2050.04,925.55 -2003.04,972.55 -1893.94,972.55 -1878.94,957.55 v1(-1630.04,957.55) ; v1(-1370.11,957.55) -1364.61,963.05 -1364.61,1230.08 -1330.07,1264.62 v1(-1330.07,1997.31) ; U1.96@-1049.84,2854.03 v1(-1017.96,2885.91)
  Bottom Signal w5: v1(-1630.04,957.55) v1(-1370.11,957.55) ; v1(-1330.07,1997.31) -1329.54,1996.78 -1327.11,1996.78 -1319.33,2004.55 -1018.45,2004.55 -600.9,2422.1 -600.9,2516.77 -770.74,2686.6 -770.74,2688.09 -975.37,2892.71 -1011.15,2892.71 v1(-1017.96,2885.91)
GPIO15: U1.95 U8.6 | length 2168.2
  Top Signal w5: v1(-1250.04,2023.55) -1115.32,1888.83 -1115.32,1634.42 -1021.01,1540.1 -1021.01,1473.95 -1008.5,1461.44 U8.6@-979.15,1461.44 ; U1.95@-1035.92,2840.11 -1000.58,2875.45 v1(-988.04,2875.45)
  Bottom Signal w5: v1(-1250.04,2023.55) -1017.54,2023.55 -615.04,2426.05 -615.04,2515.48 -781.64,2682.08 -781.64,2683.57 -973.52,2875.45 v1(-988.04,2875.45)
GPIO15_BP: J5/J7.43 U8.7 | length 1169.4
  Top Signal w5: J5/J7.43@-2050.04,1325.55 -2002.04,1373.55 v1(-1624.04,1373.55) ; v1(-1066.16,1357.55) -1063.96,1359.75 -1063.96,1378.06 -1063.03,1378.99 -1063.03,1424.06 -1045.33,1441.76 U8.7@-979.15,1441.76
  Bottom Signal w5: v1(-1624.04,1373.55) -1608.04,1357.55 v1(-1066.16,1357.55)
GPIO15_SCIRX: U8.4 U9.4 | length 3091.2
  Top Signal w5: U9.4@-980.24,3766.68 -980.24,3506.75 -955.74,3482.26 -812.76,3482.26 -777.63,3517.38 -638.45,3517.38 -609.04,3487.97 -609.04,2853.8 -655.28,2807.55 v1(-668.04,2807.55) ; v1(-821.7,1564.3) -845.22,1540.78 -845.22,1450.98 -835.99,1441.76 U8.4@-803.95,1441.76
  Bottom Signal w5: v1(-821.7,1564.3) -675.29,1564.3 -651.87,1587.72 -651.87,2116.35 -486.94,2281.28 -486.94,2557.03 -661.68,2731.77 -661.68,2801.19 v1(-668.04,2807.55)
GPIO16: J8/J6.51 U1.54 | length 2194.3
  Top Signal w5: U1.54@-1063.76,2194.25 -917.79,2048.29 -783.78,2048.29 v1(-746.04,2010.55) ; v1(-746.04,1722.28) -736.93,1722.28 -641.38,1626.73 -641.38,1021.89 -622.04,1002.55 -556.04,1002.55 -513.3,959.82 -513.3,671.82 -420.04,578.55 -297.04,578.55 J8/J6.51@-250.04,625.55
  Bottom Signal w5: v1(-746.04,1722.28) v1(-746.04,2010.55)
GPIO17: J4/J2.14 U1.55 | length 3042.1
  Top Signal w5: U1.55@-1049.84,2208.17 -900.86,2059.19 -770.27,2059.19 -374.44,1663.37 v1(-374.44,1625.15) ; J4/J2.14@-253.09,3422.5 -116.04,3285.45 -116.04,3057.55 -116.04,2571.28 -116.04,1682.95 -132.64,1666.35 v1(-132.64,1625.15)
  Bottom Signal w5: v1(-374.44,1625.15) v1(-132.64,1625.15)
GPIO18_BP: J5/J7.49 R36.1 | length 2691.3
  Top Signal w5: J5/J7.49@-2050.04,725.55 -2006.04,681.55 v1(-1604.04,681.55) ; v1(-1485.67,681.56) -1350.93,816.3 -1350.93,1223.29 -1312.8,1261.41 -1312.8,2004.46 -1322.92,2014.57 -1323.17,2014.82 v1(-1323.17,2045.83) ; v1(-813.04,2303.55) -813.04,2292.59 -803.13,2282.68 R36.1@-788.15,2282.68
  Bottom Signal w5: v1(-1604.04,681.55) v1(-1485.67,681.56) ; v1(-1323.17,2045.83) -1309.23,2059.77 -1036.82,2059.77 -813.04,2283.55 v1(-813.04,2303.55)
GPIO18_X2: R32.1 R36.2 U1.68 | length 236.7
  Top Signal w5: U1.68@-868.89,2389.12 -867.44,2389.12 -802.81,2324.49 -744.86,2324.49 -739.13,2318.76 R32.1@-739.13,2240.94
GPIO19_BP: J5/J7.50 R37.1 | length 2965
  Top Signal w5: J5/J7.50@-2050.04,625.55 -1990.59,566.1 -1554.17,566.1 -1339.21,781.06 -1339.21,1215.61 -1298.76,1256.06 -1298.76,2017.99 v1(-1305.12,2024.34) ; R37.1@-657.22,2414.36 v1(-633.04,2438.53)
  Bottom Signal w5: v1(-1305.12,2024.34) -1304.4,2024.34 -1287.34,2041.4 -1030.17,2041.4 v1(-633.04,2438.53)
GPIO19_X1: R33.1 R37.2 U1.69 | length 257.7
  Top Signal w5: U1.69@-854.97,2403.04 -790.8,2338.87 -770.72,2338.87 -739.77,2369.82 R37.2@-701.76,2369.82 -698.7,2369.82 R33.1@-654.81,2325.93
GPIO20: J8/J6.53 R34.1 U1.48 | length 5246.4
  Top Signal w5: U1.48@-1222.44,2180.33 -1250.58,2152.19 -1250.58,2119.33 -1057.54,1926.29 -844.35,1926.29 -573.04,1654.97 v1(-573.04,1637.55) ; R34.1@-808,3615.58 -758.97,3566.55 v1(-592.04,3566.55) ; v1@-573.3,1640.55 -573.3,1165.82 -546.04,1138.55 -468.04,1138.55 -427.04,1097.55 -427.04,924.63 -373.96,871.55 -296.04,871.55 J8/J6.53@-250.04,825.55 ; v1(-133.04,3536.55) -133.04,3425.04 -37.78,3329.77 -37.78,1665.37 ; v1(-70.81,1632.34) -37.78,1665.37 ; -37.78,1717.48 -37.78,1665.37
  Bottom Signal w5: v1(-592.04,3566.55) -163.04,3566.55 v1(-133.04,3536.55) ; v1(-573.04,1637.55) -538.04,1602.55 -100.6,1602.55 v1(-70.81,1632.34)
GPIO21: J4/J2.13 R35.1 U1.49 | length 3605.4
  Top Signal w5: U1.49@-1208.52,2166.41 -1234.04,2140.89 -1234.04,2118.21 -1076.64,1960.82 -802.88,1960.82 v1(-535.26,1693.19) ; R35.1@-609,3615.58 -561.61,3568.19 v1(-561.61,3378.55) ; J4/J2.13@-250.04,3325.55 -134.04,3209.55 v1(-134.04,1693.19)
  Bottom Signal w5: v1(-561.61,3378.55) -303.04,3378.55 J4/J2.13@-250.04,3325.55 ; v1(-535.26,1693.19) v1(-134.04,1693.19)
GPIO22: J4/J2.34 U1.83 | length 1158.9
  Top Signal w5: U1.83@-868.89,2673.08 -749.04,2792.92 -749.04,2821.79 -677.04,2893.79 v2(-677.04,3425.55)
  Bottom Signal w5: v2(-677.04,3425.55) J4/J2.34@-350.04,3425.55
GPIO23: J4/J2.33 U1.81 | length 1040.9
  Top Signal w5: U1.81@-841.05,2645.24 -708.61,2777.67 -647.22,2777.67 -557.04,2867.85 v2(-557.04,3325.55)
  Bottom Signal w5: v2(-557.04,3325.55) J4/J2.33@-350.04,3325.55
GPIO24: J1/J3.8 R38.1 U1.56 | length 2937.7
  Top Signal w5: J1/J3.8@-2050.04,3325.55 -2123.43,3252.17 -2123.43,2290.19 -2081.54,2248.31 -1914.04,2248.31 -1901.78,2236.04 -1901.78,2009.67 -1870.66,1978.55 v1(-1630.04,1978.55) ; U1.56@-1035.92,2222.09 -903.38,2089.55 v1(-903.04,2089.55)
  Bottom Signal w5: v1@-1630.04,1979.05 -1013.54,1979.05 ; R38.1@-1013.54,1822.72 -1013.54,1979.05 ; v1(-903.04,2089.55) -1013.54,1979.05
GPIO25: U1.57 U11.14 | length 1538.8
  Top Signal w5: v1(-1305.28,2077.03) -1271.99,2043.75 -1271.99,1243.25 -1286.69,1228.54 -1286.69,1089.04 -1277.53,1079.88 U11.14@-1236.75,1079.88 ; U1.57@-1021.01,2235.65 -1022.79,2235.65 v1(-959.18,2172.05)
  Bottom Signal w5: v1(-1305.28,2077.03) -1054.2,2077.03 v1(-959.18,2172.05)
GPIO25_BP: J8/J6.58 U11.13 | length 1124.8
  Top Signal w5: U11.13@-1236.75,1105.47 -1184.12,1105.47 -1148.04,1141.55 -1148.04,1221.62 -1133.11,1236.55 v1(-961.04,1236.55) ; v1(-530.04,1274.55) -301.04,1274.55 J8/J6.58@-250.04,1325.55
  Bottom Signal w5: v1(-961.04,1236.55) -923.04,1274.55 v1(-530.04,1274.55)
GPIO25_Q3A: U11.12 U13.6 | length 1051.3
  Top Signal w5: U11.12@-1236.75,1131.06 -1183.53,1131.06 -1161.04,1153.55 -1161.04,1230.55 -1137.78,1253.82 -953.89,1253.82 -942.78,1242.7 -942.78,1021.55 -985.77,978.55 -1028.8,978.55 -1140.51,866.83 U13.6@-1140.51,692.99
GPIO26: U1.58 U11.15 | length 1600.9
  Top Signal w5: v1(-1319.43,2110.59) -1327.89,2102.13 -1327.89,2074.97 -1284.41,2031.48 -1284.41,1249.18 -1299.04,1234.55 -1299.04,1075.55 -1277.78,1054.29 U11.15@-1236.75,1054.29 ; U1.58@-1008.08,2249.93 v1(-959.04,2200.89)
  Bottom Signal w5: v1(-1319.43,2110.59) -1049.34,2110.59 v1(-959.04,2200.89)
GPIO26_BP: J8/J6.52 U11.1 | length 1026.3
  Top Signal w5: U11.1@-1008.4,1028.7 v1(-960.04,1028.7) ; v1(-619.04,1028.55) -566.44,1028.55 -501.1,963.21 -501.1,781.04 -402.62,682.55 -293.04,682.55 J8/J6.52@-250.04,725.55
  Bottom Signal w5: v1(-960.04,1028.7) -619.19,1028.7 v1(-619.04,1028.55)
GPIO26_Q3B: U11.2 U13.7 | length 448.8
  Top Signal w5: U13.7@-1166.1,692.99 -1166.1,862.74 -1054.04,974.8 -1054.04,1046.55 -1046.3,1054.29 U11.2@-1008.4,1054.29
GPIO27: J8/J6.59 U1.59 | length 1166.8
  Top Signal w5: U1.59@-994.16,2263.85 -804.49,2074.17 -769.82,2074.17 -305.04,1609.39 -305.04,1480.55 J8/J6.59@-250.04,1425.55
GPIO28: U1.1 U6.10 | length 1094.9
  Top Signal w5: U6.10@-1238.35,3918.23 -1259.83,3918.23 -1273.33,3904.74 -1273.33,3456.66 -1211.3,3394.63 -1211.3,2926.41 U1.1@-1194.6,2909.71 ; U1.1@-1194.6,2909.4 U1.1@-1175.75,2890.55
GPIO28_BP: J1/J3.3 U6.2 | length 666.7
  Top Signal w5: J1/J3.3@-2050.04,3825.55 -1995.13,3880.46 -1504.83,3880.46 -1486.74,3898.54 U6.2@-1413.54,3898.54
GPIO28_SCIRX: U6.9 U9.7 | length 301.4
  Top Signal w5: U6.9@-1238.35,3898.54 v1(-1073.11,3898.54) ; v1(-980.24,3898.54) U9.7@-980.24,3941.88
  Bottom Signal w5: v1(-1073.11,3898.54) v1(-980.24,3898.54)
GPIO29: U1.100 U6.6 | length 1000.5
  Top Signal w5: U6.6@-1238.35,3839.49 -1238.35,3447.03 -1086.61,3295.29 -1086.61,2928.62 U1.100@-1105.52,2909.71
GPIO29_BP: J1/J3.4 J1/J3.5 U6.4 | length 864.8
  Top Signal w5: J1/J3.5@-2050.04,3625.55 -2050.04,3719.42 J1/J3.4@-2046.07,3723.39 ; J1/J3.4@-2050.04,3725.55 -2002.54,3773.05 -2002.54,3854.05 -1987.04,3869.55 -1502.87,3869.55 -1492.49,3859.17 U6.4@-1413.54,3859.17
  Bottom Signal w5: J1/J3.4@-2050.04,3725.55 J1/J3.4@-2050.04,3743.03
GPIO29_SCITX: U6.7 U9.9 | length 287.5
  Top Signal w5: U6.7@-1238.35,3859.17 -1043.43,3859.17 -1019.61,3882.99 U9.9@-1019.61,3941.88
GPIO30: U1.98 U11.4 | length 2499.4
  Top Signal w5: U1.98@-1077.68,2881.87 -1042.87,2916.67 v1(-1042.87,2917.05) ; U11.4@-1008.4,1105.47 -964.12,1105.47 v1(-964.04,1105.55) ; v1(-901.04,1105.55) -767.04,1105.55 -728.78,1143.82 -728.78,1628.86 v1(-782.31,1682.4)
  Bottom Signal w5: v1(-1042.87,2917.05) -1029.11,2930.82 -982.62,2930.82 -748.92,2697.12 -748.92,2695.63 -575.24,2521.94 -575.24,2378.27 -812.04,2141.47 -812.04,1712.13 v1(-782.31,1682.4) ; v1(-964.04,1105.55) v1(-901.04,1105.55)
GPIO30_BP: J8/J6.57 U11.3 | length 833.6
  Top Signal w7.87: U11.3@-1008.4,1079.88 v1(-960.56,1079.88) ; v1(-556.04,1195.55) -538.04,1177.55 -298.04,1177.55 J8/J6.57@-250.04,1225.55
  Bottom Signal w7.87: v1(-960.56,1079.88) -785.21,1079.88 -669.54,1195.55 v1(-556.04,1195.55)
GPIO30_Q3I: U11.5 U13.8 | length 536.5
  Top Signal w5: U13.8@-1191.69,692.99 -1191.69,858.9 -1067.04,983.55 -1067.04,1110.83 -1046.8,1131.06 U11.5@-1008.4,1131.06
GPIO31: J4/J2.17 U1.99 | length 1997.2
  Top Signal w5: U1.99@-1091.6,2895.79 -1066.04,2921.35 -1066.04,3290.27 -1216.17,3440.41 -1216.17,3791.8 -1174.11,3833.86 -886.35,3833.86 v1(-873.04,3820.55)
  Bottom Signal w5: v1(-873.04,3820.55) -858.65,3806.16 -413.99,3806.16 -384.38,3776.55 -301.04,3776.55 J4/J2.17@-250.04,3725.55
GPIO32: J4/J2.18 R39.2 U1.64 | length 3807.7
  Top Signal w5: U1.64@-924.56,2333.44 -895.04,2303.92 -895.04,2227.55 v1(-832.04,2164.55) -774.38,2106.89 -755.65,2106.89 -319.31,1670.55 v1(-217.91,1670.55) ; J4/J2.18@-250.04,3825.55 -203.35,3825.55 -162.26,3784.46 -162.26,3408.81 -73.04,3319.59 v1(-73.04,1670.55) v1@-75.23,1670.55
  Bottom Signal w5: R39.2@-877.09,1822.72 R39.2@-868.82,1822.72 -884.99,1838.89 -884.99,2111.6 v1(-832.04,2164.55) ; v1(-217.91,1670.55) v1(-73.04,1670.55) v1@-72.75,1670.55
GPIO33: J8/J6.71 U1.53 | length 2404.6
  Top Signal w5: U1.53@-1077.68,2180.33 -939.83,2042.48 ; -939.48,2042.48 -939.83,2042.48 ; J8/J6.71@-350.04,625.55 -307.32,668.27 -225.63,668.27 -94.42,799.48 -94.42,1085.8 -71.69,1108.52 v1(-71.69,1585.2) ; v1(-327.99,1585.2) -377.2,1585.2 -397.97,1605.96 -397.97,1655.08 -721.5,1978.6 -738.51,1978.6 -763.3,2003.4 -763.3,2003.68 -795.61,2035.98 -933.33,2035.98 -939.83,2042.48
  Bottom Signal w5: v1(-327.99,1585.2) v1(-71.69,1585.2)
GPIO34: J1/J3.10 U1.94 | length 1606.9
  Top Signal w5: J1/J3.10@-2050.04,3125.55 -2007.04,3168.55 -1931.04,3168.55 -1895.04,3132.55 -1895.04,3092.55 -1839.04,3036.55 -1612.46,3036.55 v1(-1595.51,3053.5) ; U1.94@-1022,2826.19 -994.05,2854.14 -984.93,2854.14 -957.04,2882.04 v2(-957.04,3160.55)
  Bottom Signal w5: v1(-1595.51,3053.5) -1584.47,3064.55 -1552.71,3064.55 -1456.97,3160.29 -957.3,3160.29 v2(-957.04,3160.55)
GPIO35: J8/J6.75 R44.1 U1.63 | length 1948.4
  Top Signal w5: v1(-969.04,2350.55) -969.04,2350.08 U1.63@-938.48,2319.53 -910.04,2291.08 -910.04,2218.14 -787.89,2095.98 -760.16,2095.98 -312.66,1648.48 -265.33,1648.48 -188.13,1571.29 -188.13,1032.42 -243,977.55 -302.04,977.55 J8/J6.75@-350.04,1025.55
  GND w5: v1@-972.07,2351.55 -971.07,2350.55 v1(-969.04,2350.55)
  Bottom Signal w5: R44.1@-977.47,2392.99 -958.18,2373.69 -958.18,2361.41 v1(-969.04,2350.55)
GPIO37: J8/J6.76 R45.1 U1.61 | length 1819.5
  Top Signal w5: v1(-1008.08,2321.31) -995.94,2321.31 U1.61@-966.32,2291.69 -924.04,2249.4 -924.04,2216.71 -792.4,2085.08 -765.31,2085.08 -315.42,1635.2 -267.46,1635.2 -199.04,1566.78 -199.04,1109.55 -231.04,1077.55 -302.04,1077.55 J8/J6.76@-350.04,1125.55
  Bottom Signal w5: R45.1@-1045.47,2321.14 -1045.3,2321.31 v1(-1008.08,2321.31)
GPIO40: U1.80 U13.3 | length 2678.6
  Top Signal w5: U13.3@-1063.74,692.99 -1063.74,844.85 -996.04,912.55 -790.84,912.55 -680.04,1023.35 v1(-680.04,1612.55) ; U1.80@-827.13,2631.32 v1(-698.04,2760.41)
  Bottom Signal w5: v1(-698.04,2760.41) -698.04,2738.77 -683.49,2724.22 -683.49,2722.74 -508.76,2548 -508.76,2294.83 -680.04,2123.55 -680.04,1827.39 -679.87,1827.22 -679.87,1803.88 -680.04,1803.71 v1(-680.04,1612.55)
GPIO41: U1.82 U13.4 | length 2709.9
  Top Signal w5: U13.4@-1089.33,692.99 -1089.33,852.26 -1008.04,933.55 -793.13,933.55 -698.04,1028.65 v1(-698.04,1642.55) ; U1.82@-854.97,2659.16 v1(-733.54,2780.58)
  Bottom Signal w5: v1(-733.54,2780.58) -733.54,2758.85 -694.4,2719.71 -694.4,2718.22 -519.66,2543.48 -519.66,2299.35 -690.94,2128.07 -690.94,1822.87 -690.78,1822.7 -690.78,1808.4 -698.04,1801.14 v1(-698.04,1642.55)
